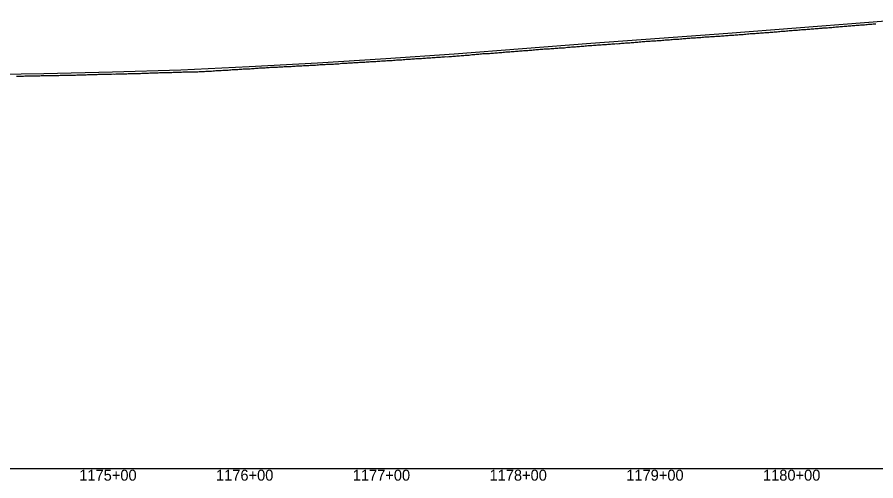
# Model space of a CAD drawing. Extents: x -3793 to 50787, y -1075 to 6138.
# Drawn here: x 4808 to 5436, y -1009 to -670 of the extents above; entities that cross this region are included whole.
import ezdxf

# ---------------------------------------------------------------- set-up
doc = ezdxf.new("R2010")
doc.units = 0
for name, color, linetype in [('RD_DDB_Profile_EX', 7, 'Continuous'), ('RD_DDB_Profile_PR', 7, 'Continuous'), ('RD_DDB_StaTX', 7, 'Continuous'), ('RD_GPK_Profile_Cell', 7, 'Continuous')]:
    doc.layers.add(name, color=color, linetype=linetype)

msp = doc.modelspace()

# ---------------------------------------------------------------- linework, layer by layer
at = {"layer": 'RD_DDB_Profile_EX'}
for points in [[(5373.365808, -680.00745), (5374.368676, -679.95665), (5375.361587, -679.806745), (5376.364393, -679.706535), (5377.36726, -679.7055), (5378.360041, -679.65561), (5379.362853, -679.55516), (5380.365721, -679.404475), (5381.358612, -679.30419), (5382.361476, -679.204115), (5383.364181, -679.204185), (5384.367049, -679.20336), (5385.359931, -679.053215), (5386.362767, -678.95276), (5387.365635, -678.902195), (5388.358386, -678.75282), (5389.36125, -678.702345), (5390.364096, -678.65178), (5391.356959, -678.60126), (5392.359705, -678.50179), (5393.361841, -678.401375), (5394.35499, -678.3008), (5395.358119, -678.2003), (5395.962757, -678.16986), (5396.361357, -678.1502), (5396.835272, -678.12612), (5397.353755, -678.10021), (5397.789619, -678.078275), (5398.35704, -678.05027), (5399.360443, -677.950745), (5400.363848, -677.90128), (5401.357326, -677.851695), (5402.35953, -677.75125), (5403.362932, -677.65178), (5404.356417, -677.602225), (5405.359797, -677.452925), (5406.363201, -677.353565), (5407.355505, -677.303135), (5408.358912, -677.303065), (5409.362282, -677.153835), (5410.355783, -677.05457), (5411.357998, -676.954255), (5412.361367, -676.85477), (5413.354868, -676.904715), (5414.358274, -676.80564), (5415.361623, -676.656645), (5416.353957, -676.55644), (5417.357357, -676.506215), (5418.360763, -676.406715), (5419.364102, -676.357205), (5420.357628, -676.208095), (5421.359844, -676.108195), (5422.363185, -676.10746), (5423.356707, -676.008345), (5424.360112, -675.90921), (5425.36343, -675.859715), (5426.355795, -675.759295), (5427.35919, -675.70941), (5428.35953, -675.660315), (5429.352899, -675.5109), (5430.356063, -675.411415), (5431.35843, -675.311345), (5432.351811, -675.26242), (5432.688149, -675.260575), (5433.691676, -675.16107), (5434.68394, -675.111105), (5435.686045, -675.060605)], [(5273.691569, -687.462665), (5274.694128, -687.413145), (5275.696687, -687.364245), (5276.689751, -687.263655), (5277.69231, -687.21293), (5278.695366, -687.211275), (5279.688056, -687.013465), (5280.69099, -686.91297), (5281.693549, -686.863455), (5282.686731, -686.813475), (5283.689173, -686.81337), (5284.691731, -686.71385), (5285.694787, -686.56397), (5286.687355, -686.51377), (5287.690411, -686.41328), (5288.69297, -686.364385), (5289.686155, -686.411995), (5290.688594, -686.213675), (5291.691159, -686.21286), (5292.694208, -686.113665), (5293.686783, -685.964705), (5294.689832, -685.8642), (5295.692391, -685.765345), (5296.685456, -685.715345), (5297.688015, -685.615255), (5298.69107, -685.56472), (5299.683765, -685.515165), (5300.686204, -685.415675), (5301.689253, -685.365155), (5302.691818, -685.36436), (5303.684877, -685.21569), (5304.687442, -685.166225), (5305.690491, -685.064425), (5306.683059, -685.0155), (5307.685625, -684.96601), (5308.688674, -684.866135), (5309.681381, -684.766585), (5310.684298, -684.6654), (5311.686863, -684.61591), (5312.689912, -684.564745), (5313.682487, -684.46648), (5314.685536, -684.415935), (5315.688095, -684.415825), (5316.68067, -684.3649), (5317.683719, -684.26442), (5318.686284, -684.214215), (5319.689333, -684.11441), (5320.681908, -684.01548), (5321.684957, -684.01368), (5322.687523, -683.96345), (5323.680091, -683.815205), (5324.683147, -683.764715), (5325.685706, -683.615195), (5326.680233, -683.613975), (5327.682703, -683.515125), (5328.685714, -683.465295), (5329.688317, -683.415115), (5330.681462, -683.36389), (5331.683933, -683.263665), (5332.686536, -683.16481), (5333.679685, -683.06495), (5334.682152, -683.06473), (5335.685163, -682.91562), (5336.677908, -682.81535), (5337.680909, -682.814195), (5338.683382, -682.763945), (5339.685985, -682.6651), (5340.679131, -682.56527), (5341.681601, -682.51359), (5342.684606, -682.41387), (5343.67736, -682.26708), (5344.680223, -682.216555), (5345.682825, -682.164235), (5346.685836, -682.065165), (5347.372155, -682.06457), (5348.374887, -681.964785), (5349.377627, -681.91456), (5350.370613, -681.863365), (5351.373352, -681.76292), (5352.376222, -681.71186), (5353.369195, -681.56258), (5354.371939, -681.46241), (5355.374686, -681.41137), (5356.367653, -681.36032), (5357.370521, -681.309915), (5358.373282, -681.20952), (5359.366113, -681.159845), (5360.36898, -681.0605), (5361.371846, -680.910565), (5362.364696, -680.859545), (5363.367562, -680.85774), (5364.370305, -680.808115), (5365.373082, -680.659095), (5366.366022, -680.559015), (5367.36889, -680.508135), (5368.371757, -680.45692), (5369.364481, -680.358065), (5370.367349, -680.258375), (5371.370216, -680.208245), (5372.363065, -680.00699), (5373.365808, -680.00745)], [(5174.064923, -694.96761), (5175.057992, -694.91704), (5176.060778, -694.817245), (5177.063456, -694.71703), (5178.066391, -694.666515), (5179.05906, -694.56768), (5180.061994, -694.51643), (5181.064672, -694.46546), (5182.05774, -694.414925), (5183.060275, -694.36465), (5184.063209, -694.215625), (5185.06614, -694.0679), (5186.058809, -694.16697), (5187.061744, -693.91575), (5188.064421, -693.76696), (5189.057483, -693.764985), (5190.060025, -693.71476), (5191.062959, -693.615655), (5192.055768, -693.51608), (5193.058563, -693.46489), (5194.061494, -693.463105), (5195.064175, -693.41285), (5196.057097, -693.31368), (5197.059778, -693.2648), (5198.062709, -693.16237), (5199.055515, -693.11271), (5200.058313, -693.06165), (5201.060994, -692.9627), (5202.054045, -692.911585), (5203.056847, -692.81119), (5204.059528, -692.71286), (5205.06246, -692.661805), (5206.05526, -692.61087), (5207.058063, -692.510495), (5208.060744, -692.51086), (5209.053789, -692.36166), (5210.056347, -692.2127), (5211.059279, -692.162265), (5212.062213, -692.11182), (5213.054882, -692.01341), (5214.057817, -691.96292), (5215.060494, -691.91279), (5216.053537, -691.812255), (5217.056098, -691.762105), (5218.059029, -691.61284), (5219.051822, -691.563235), (5220.054633, -691.462755), (5221.057567, -691.361705), (5222.060245, -691.312745), (5223.053282, -691.21218), (5224.055848, -691.112665), (5225.058783, -691.012725), (5226.051566, -690.914295), (5227.054387, -690.91264), (5228.057064, -690.86314), (5229.059999, -690.76263), (5230.052922, -690.71205), (5231.055602, -690.61254), (5232.058534, -690.46256), (5233.051314, -690.41354), (5234.054138, -690.36299), (5234.709602, -690.361825), (5235.702507, -690.261715), (5236.705232, -690.212195), (5237.70801, -690.2117), (5238.700919, -690.20991), (5239.703693, -690.060565), (5240.706418, -689.9621), (5241.709196, -689.86161), (5242.695314, -689.763105), (5243.698256, -689.663105), (5244.700814, -689.613105), (5245.6935, -689.562975), (5246.696438, -689.61193), (5247.699002, -689.46353), (5248.702053, -689.36192), (5249.694738, -689.31176), (5250.697677, -689.212915), (5251.700241, -689.21287), (5252.692924, -689.063875), (5253.695865, -689.01334), (5254.698423, -688.96271), (5255.691593, -688.912155), (5256.694047, -688.8132), (5257.697097, -688.662695), (5258.699662, -688.61319), (5259.692348, -688.56421), (5260.695286, -688.46424), (5261.697844, -688.3642), (5262.691022, -688.263585), (5263.693468, -688.16411), (5264.696518, -688.11415), (5265.699083, -688.014685), (5266.692142, -687.96293), (5267.694707, -687.865175), (5268.697266, -687.81635), (5269.690446, -687.714495), (5270.692889, -687.665045), (5271.695945, -687.563905), (5272.688633, -687.514355), (5273.691569, -687.462665)], [(5074.039484, -702.11455), (5075.042285, -702.06395), (5076.044964, -702.06388), (5077.037858, -702.014305), (5078.040658, -701.91545), (5079.043459, -701.91597), (5080.046121, -701.867195), (5081.039032, -701.816245), (5082.041833, -701.81383), (5083.044642, -701.714835), (5084.047296, -701.61603), (5085.040215, -701.51644), (5086.043016, -701.46692), (5087.045816, -701.4174), (5088.048454, -701.317065), (5089.036057, -701.317445), (5090.038718, -701.21961), (5091.287595, -701.069965), (5092.290142, -700.970465), (5093.283393, -700.96988), (5094.285768, -700.92038), (5095.288835, -700.86987), (5096.291383, -700.72214), (5097.284633, -700.670645), (5098.287008, -700.619405), (5099.290076, -700.519775), (5100.28281, -700.4702), (5101.285702, -700.41969), (5102.288249, -700.37019), (5103.291308, -700.31884), (5104.284049, -700.26748), (5105.286933, -700.167905), (5106.28949, -700.11747), (5107.282729, -699.969525), (5108.285115, -699.870875), (5109.288174, -699.818665), (5110.29073, -699.81826), (5111.283969, -699.766895), (5112.286356, -699.66818), (5113.289415, -699.616885), (5114.282154, -699.5681), (5115.284529, -699.51856), (5116.287597, -699.51723), (5117.290144, -699.415015), (5118.283394, -699.2163), (5119.28577, -699.16671), (5120.288837, -699.11629), (5121.28157, -699.06664), (5122.285828, -699.11452), (5123.288418, -699.014875), (5124.291442, -698.96366), (5125.284038, -698.865685), (5126.287062, -698.71615), (5127.289652, -698.666545), (5128.282682, -698.616925), (5129.285272, -698.517345), (5130.288296, -698.465225), (5131.290886, -698.3656), (5132.283916, -698.21684), (5133.286506, -698.216395), (5134.28953, -698.11683), (5135.282125, -697.968045), (5136.28515, -697.917595), (5137.287732, -697.91719), (5138.280936, -697.86668), (5139.283352, -697.719685), (5140.286384, -697.619175), (5141.288966, -697.51882), (5142.282003, -697.468255), (5143.284585, -697.36959), (5144.287617, -697.31742), (5145.280205, -697.217805), (5146.283237, -697.069815), (5147.285819, -696.922035), (5148.288851, -696.869805), (5149.064708, -696.819575), (5150.067391, -696.769245), (5151.07032, -696.719565), (5152.062994, -696.670825), (5153.065924, -696.66785), (5154.068602, -696.569165), (5155.061689, -696.419385), (5156.064457, -696.417295), (5157.067139, -696.26857), (5158.070069, -696.217285), (5159.062743, -696.216875), (5160.065673, -696.117205), (5161.068355, -696.01767), (5162.061276, -695.965565), (5163.063958, -695.866785), (5164.066888, -695.81711), (5165.059964, -695.667305), (5166.062491, -695.666255), (5167.065426, -695.61579), (5168.068104, -695.516245), (5169.061025, -695.416475), (5170.063707, -695.41694), (5171.066637, -695.31721), (5172.059464, -695.11839), (5173.062241, -695.067125), (5174.064923, -694.96761)], [(4974.005324, -708.01843), (4975.008863, -708.01896), (4976.001011, -707.968505), (4977.003096, -707.91799), (4978.00516, -707.866785), (4978.998922, -707.768065), (4980.000848, -707.66753), (4981.002912, -707.617), (4982.006473, -707.51822), (4982.998621, -707.46775), (4984.000685, -707.367195), (4985.00275, -707.366025), (4986.006291, -707.31528), (4986.99844, -707.26548), (4988.000523, -707.21498), (4989.002587, -707.16389), (4990.006129, -707.11498), (4990.998278, -707.015125), (4992.000343, -706.96347), (4993.003903, -706.864555), (4993.996164, -706.814685), (4994.998116, -706.813065), (4996.000181, -706.763095), (4997.003725, -706.713065), (4997.99589, -706.662655), (4998.997955, -706.61267), (5000.00002, -706.512645), (5001.003564, -706.51267), (5001.995714, -706.46175), (5002.997779, -706.361725), (5004.001338, -706.31225), (5004.993581, -706.310865), (5005.995553, -706.260395), (5006.997618, -706.21036), (5008.001164, -706.1613), (5008.993327, -706.011745), (5009.995392, -705.911195), (5010.998939, -705.91088), (5012.001005, -705.86078), (5012.993155, -705.859935), (5013.995232, -705.85905), (5014.998779, -705.759545), (5015.991004, -705.70951), (5016.992995, -705.609355), (5017.995061, -705.558145), (5018.998609, -705.509), (5019.990838, -705.50823), (5020.991867, -705.45742), (5021.995353, -705.35858), (5022.997481, -705.30839), (5023.989684, -705.208245), (5024.991812, -705.20712), (5025.995299, -705.207025), (5026.987559, -705.156915), (5027.98963, -704.95723), (5028.993117, -704.857495), (5029.995246, -704.856965), (5030.987499, -704.856515), (5031.989579, -704.755985), (5032.993066, -704.70652), (5034.034726, -704.65589), (5035.036872, -704.65514), (5036.038983, -704.55443), (5037.031236, -704.45416), (5038.033382, -704.45349), (5039.035528, -704.55262), (5040.037654, -704.30257), (5041.029892, -704.252115), (5042.032038, -704.301465), (5043.034184, -704.200975), (5044.036326, -704.050545), (5045.172048, -703.9), (5046.03125, -703.9005), (5047.034047, -703.85104), (5048.036843, -703.801605), (5049.029628, -703.75208), (5050.032408, -703.70366), (5051.035222, -703.603025), (5052.038018, -703.60253), (5053.030811, -703.55311), (5054.033584, -703.403815), (5055.03638, -703.3544), (5056.039176, -703.30517), (5057.031986, -703.255685), (5058.034741, -703.205845), (5059.037537, -703.20616), (5060.040334, -703.1567), (5061.03316, -703.00745), (5062.035961, -703.00771), (5063.038695, -702.95825), (5064.041491, -702.859495), (5065.034335, -702.759255), (5066.037135, -702.710185), (5067.039853, -702.61076), (5068.042649, -702.61045), (5069.035509, -702.609985), (5070.03831, -702.51094), (5071.04101, -702.411445), (5072.043806, -702.411425), (5073.036684, -702.31237), (5074.039484, -702.11455)], [(4873.796354, -711.82104), (4874.799565, -711.771545), (4875.792004, -711.819365), (4876.795215, -711.77073), (4877.806808, -711.720255), (4878.810239, -711.768035), (4879.802495, -711.719455), (4880.805926, -711.719915), (4881.808117, -711.66858), (4882.801591, -711.61998), (4883.803804, -711.57043), (4884.807213, -711.61908), (4885.809426, -711.56955), (4886.8029, -711.520065), (4887.805091, -711.51783), (4888.808522, -711.470075), (4889.810536, -711.46873), (4890.804208, -711.46832), (4891.8064, -711.3697), (4892.809808, -711.32106), (4893.802087, -711.36888), (4894.805494, -711.369305), (4895.807709, -711.367985), (4896.811117, -711.270235), (4897.803373, -711.268945), (4898.806803, -711.21939), (4899.808995, -711.218955), (4900.801274, -711.2186), (4901.804682, -711.217215), (4902.806874, -711.11771), (4903.810304, -711.069035), (4904.802561, -710.97045), (4905.805991, -710.92184), (4906.808183, -710.920455), (4907.801655, -710.87191), (4908.80387, -710.87054), (4909.807277, -710.86918), (4910.809492, -710.819655), (4911.802964, -710.771085), (4912.805156, -710.720615), (4913.808586, -710.77018), (4914.801022, -710.767995), (4915.804272, -710.768415), (4916.806465, -710.767105), (4917.809872, -710.71841), (4918.802152, -710.66898), (4919.805558, -710.57125), (4920.807751, -710.56897), (4921.801429, -710.470405), (4922.803438, -710.46995), (4923.806867, -710.469485), (4924.80906, -710.36996), (4925.801318, -710.319575), (4926.804746, -710.37004), (4927.80694, -710.320475), (4928.800615, -710.270115), (4929.802626, -710.219665), (4930.806032, -710.219195), (4931.808248, -710.21878), (4932.801901, -710.121105), (4933.803935, -710.16975), (4934.807341, -710.21928), (4935.799778, -710.16711), (4936.803027, -710.11843), (4937.805221, -710.06802), (4938.808649, -710.06844), (4939.801087, -710.06809), (4940.804313, -710.01757), (4941.80653, -710.01629), (4942.800184, -709.96578), (4943.802216, -709.91726), (4944.805621, -709.8195), (4945.807816, -709.71907), (4946.801493, -709.670505), (4947.803502, -709.670055), (4948.80693, -709.620515), (4949.800338, -709.57097), (4951.008426, -709.521045), (4952.010488, -709.42147), (4953.01255, -709.27185), (4954.00617, -709.222435), (4955.008233, -709.17192), (4956.010322, -709.170565), (4957.003942, -709.121125), (4958.006005, -709.021495), (4959.008068, -708.92182), (4960.010131, -708.871285), (4961.003777, -708.87107), (4962.00584, -708.870555), (4963.007903, -708.77084), (4964.01144, -708.623835), (4965.003588, -708.572525), (4966.005675, -708.521185), (4967.007738, -708.5191), (4968.00136, -708.470475), (4969.003424, -708.469175), (4970.005487, -708.319405), (4971.007551, -708.220325), (4972.001196, -708.121), (4973.00326, -708.019695), (4974.005324, -708.01843)], [(4807.262187, -713.25759), (4808.265072, -713.2571), (4809.267895, -713.30632), (4810.260824, -713.255785), (4811.263708, -713.255325), (4812.266593, -713.254625), (4813.259461, -713.204535), (4814.262346, -713.154045), (4815.265231, -713.153395), (4816.257941, -713.15396), (4817.260826, -713.153475), (4818.263711, -713.15285), (4819.266595, -713.1025), (4820.259464, -713.05194), (4821.262349, -713.101385), (4822.265234, -713.05096), (4823.258103, -713.05038), (4824.261091, -713.00008), (4825.264527, -712.900555), (4826.258037, -712.90109), (4827.261477, -712.90156), (4828.263651, -712.9011), (4829.257167, -712.90149), (4830.260605, -712.85201), (4831.264022, -712.852455), (4832.257551, -712.852825), (4833.260987, -712.80325), (4834.264426, -712.80349), (4835.267825, -712.8041), (4836.261365, -712.80458), (4837.264804, -712.804755), (4838.268189, -712.80489), (4839.261741, -712.705915), (4840.265179, -712.656655), (4841.267311, -712.655925), (4842.260867, -712.65641), (4843.264305, -712.65683), (4844.267744, -712.607255), (4845.261248, -712.60813), (4846.264676, -712.60816), (4847.268114, -712.509015), (4848.261617, -712.50907), (4849.265043, -712.558535), (4850.26848, -712.558425), (4851.262087, -712.459875), (4852.265407, -712.41135), (4853.268844, -712.361795), (4854.271043, -712.410825), (4855.264532, -712.41074), (4856.267968, -712.36114), (4857.271405, -712.31154), (4858.264907, -712.312005), (4859.268328, -712.2137), (4860.271764, -712.214145), (4861.265404, -712.213955), (4862.268684, -712.214365), (4863.27212, -712.214785), (4864.265773, -712.116035), (4865.269037, -712.01725), (4866.271243, -712.01681), (4867.264901, -711.96734), (4868.26816, -711.96779), (4869.271595, -711.919085), (4870.265265, -711.91964), (4871.268682, -711.870985), (4872.271943, -711.87149), (4872.793933, -711.87152), (4873.796354, -711.82104)]]:
    msp.add_lwpolyline(points, dxfattribs=at)
at = {"layer": 'RD_DDB_Profile_PR'}
msp.add_lwpolyline([(4777.33, -712.1165), (4827.33, -711.3015), (4877.33, -710.144), (4927.33, -708.744), (4977.33, -706.3015), (5027.33, -703.4885), (5077.33, -700.3855), (5127.33, -697.0645), (5177.33, -693.1035), (5227.33, -689.299), (5277.33, -685.6315), (5327.33, -681.95), (5377.33, -678.1055), (5427.33, -674.111), (5477.33, -670.221)], dxfattribs=at)
at = {"layer": 'RD_GPK_Profile_Cell'}
msp.add_line((1000, -1000), (46610.921919, -1000), dxfattribs=at)

# ---------------------------------------------------------------- texts
at = {"layer": 'RD_DDB_StaTX'}
for s, p in [('1175+00', (4853.125471, -1009)), ('1175+00', (4853.125471, -1009)), ('1176+00', (4953.125471, -1009)), ('1176+00', (4953.125471, -1009)), ('1177+00', (5053.125471, -1009)), ('1177+00', (5053.125471, -1009)), ('1178+00', (5153.125471, -1009)), ('1178+00', (5153.125471, -1009)), ('1179+00', (5253.125471, -1009)), ('1179+00', (5253.125471, -1009)), ('1180+00', (5353.125471, -1009)), ('1180+00', (5353.125471, -1009))]:
    msp.add_text(s, height=8, dxfattribs=at).set_placement(p)

doc.saveas('drawing.dxf')
